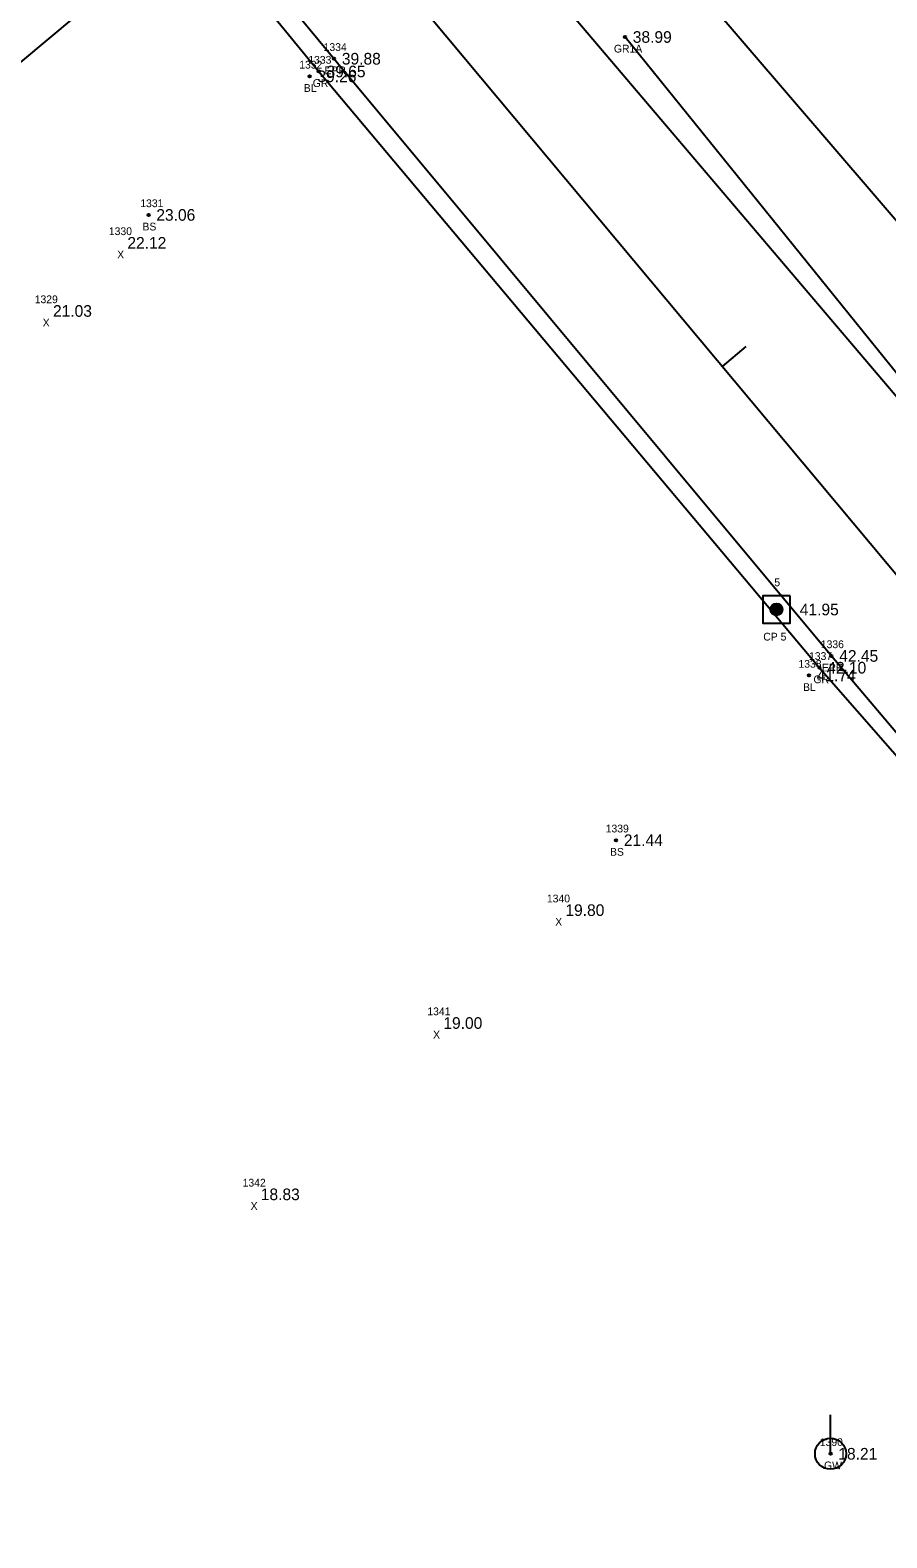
# Model space of a CAD drawing. Extents: x 2042117 to 2045853, y 303080 to 309569.
# Drawn here: x 2043251.6 to 2043361.9, y 305904.8 to 306099 of the extents above; entities that cross this region are included whole.
import ezdxf

# ---------------------------------------------------------------- set-up
doc = ezdxf.new("R2010")
doc.units = 0
for name, color, linetype in [('RD_DTM_BkLn_txCode', 7, 'Continuous'), ('RD_EX_GuardRail', 7, 'Continuous'), ('RD_EX_GuardRail_txCode', 7, 'Continuous'), ('RD_EX_Misc_txCode', 7, 'Continuous'), ('RD_EX_Road', 7, 'Continuous'), ('RD_EX_Road_txCode', 7, 'Continuous'), ('RD_EX_TX_GuardRail_ELEV', 7, 'Continuous'), ('RD_EX_TX_Misc_ELEV', 7, 'Continuous'), ('RD_EX_TX_Road_ELEV', 7, 'Continuous'), ('RD_EX_TX_UT_ELEV', 7, 'Continuous'), ('RD_EX_UT', 7, 'Continuous'), ('RD_EX_UT_txCode', 7, 'Continuous'), ('RD_EX_VEG', 7, 'Continuous'), ('RD_HC_Cl', 7, 'Continuous'), ('RD_HC_Data', 7, 'Continuous'), ('RD_HC_Data_Tic', 7, 'Continuous'), ('RD_HC_Survey', 7, 'Continuous'), ('RD_HC_Survey_ELEV', 7, 'Continuous'), ('RD_HC_Survey_txCode', 7, 'Continuous'), ('RD_SMD_Locator', 7, 'Continuous')]:
    doc.layers.add(name, color=color, linetype=linetype)

msp = doc.modelspace()

# ---------------------------------------------------------------- linework, layer by layer
at = {"layer": 'RD_EX_GuardRail'}
for points in [[(2042989.52, 306565.65), (2042994.63, 306555.31), (2043016.03, 306510.44), (2043038.99, 306465.35), (2043062.42, 306421.45), (2043086.95, 306378), (2043112.8, 306335.35), (2043139.38, 306293.6), (2043167.12, 306252.13), (2043196.01, 306211.01), (2043226.01, 306171.01), (2043257.1, 306132.34), (2043288.76, 306093.67), (2043353.25, 306016.86), (2043419.08, 305941.69), (2043443.37, 305914.98)], [(2043328.2, 306098.11), (2043376.89, 306037.83), (2043391.98, 306019.15), (2043438.03, 305959.17), (2043441.35, 305955), (2043457.81, 305935.14)]]:
    msp.add_lwpolyline(points, dxfattribs=at)
at = {"layer": 'RD_EX_Road'}
for points in [[(2043137.38, 306350.66), (2043162.88, 306309.77), (2043190.74, 306268.8), (2043219.18, 306228.69), (2043249.32, 306189.21), (2043279.47, 306150.9), (2043310.9, 306113.33), (2043375.86, 306036.86), (2043413.21, 305990.46), (2043437.78, 305959.09), (2043453.01, 305940), (2043456.21, 305936.08), (2043457.42, 305934.8)], [(2043115.12, 306336.87), (2043141.61, 306295.02), (2043169.3, 306253.51), (2043198.36, 306212.75), (2043228.29, 306172.85), (2043259.02, 306133.68), (2043290.73, 306095.31), (2043354.79, 306018.38), (2043419.43, 305942.01), (2043438.08, 305920.77), (2043442.86, 305915.34)]]:
    msp.add_lwpolyline(points, dxfattribs=at)
at = {"layer": 'RD_EX_UT'}
msp.add_line((2043354.67, 305915.6), (2043354.67, 305920.6), dxfattribs=at)
msp.add_circle((2043354.67, 305915.6), 2, dxfattribs=at)
at = {"layer": 'RD_EX_VEG'}
msp.add_lwpolyline([(2043030.11, 306588.1), (2043035.72, 306574.19), (2043060.12, 306522.02), (2043088.59, 306466.9), (2043098.93, 306441.29), (2043120.97, 306400.06), (2043177.31, 306317.21), (2043201.76, 306279.58), (2043229.83, 306237.41), (2043260.65, 306197.8), (2043289.37, 306160.32), (2043322.23, 306122.17), (2043376.5, 306058.9), (2043456.79, 305961.76), (2043477.52, 305946.76)], dxfattribs=at)
at = {"layer": 'RD_HC_Cl'}
msp.add_line((2043284.3, 306123.24), (2045221.31, 303804), dxfattribs=at)
at = {"layer": 'RD_HC_Data'}
msp.add_line((2043284.29, 306123.24), (2043173.02, 306030.31), dxfattribs=at)
at = {"layer": 'RD_HC_Data_Tic'}
msp.add_line((2043340.74, 306055.66), (2043343.81, 306058.22), dxfattribs=at)
at = {"layer": 'RD_HC_Survey'}
for p, q in [((2043346.97, 306024.18), (2043346.97, 306024.54)), ((2043346.99, 306024.1), (2043346.99, 306024.62)), ((2043347.02, 306024.04), (2043347.02, 306024.68)), ((2043347.04, 306023.99), (2043347.04, 306024.73)), ((2043347.07, 306023.95), (2043347.07, 306024.77)), ((2043347.09, 306023.91), (2043347.09, 306024.81)), ((2043347.11, 306023.88), (2043347.11, 306024.84)), ((2043347.14, 306023.85), (2043347.14, 306024.87)), ((2043347.16, 306023.82), (2043347.16, 306024.9)), ((2043347.19, 306023.8), (2043347.19, 306024.92)), ((2043347.21, 306023.78), (2043347.21, 306024.94)), ((2043347.24, 306023.76), (2043347.24, 306024.96)), ((2043347.26, 306023.74), (2043347.26, 306024.98)), ((2043347.29, 306023.72), (2043347.29, 306025)), ((2043347.31, 306023.7), (2043347.31, 306025.02)), ((2043347.34, 306023.69), (2043347.34, 306025.03)), ((2043347.36, 306023.68), (2043347.36, 306025.04)), ((2043347.39, 306023.66), (2043347.39, 306025.06)), ((2043347.41, 306023.65), (2043347.41, 306025.07)), ((2043347.44, 306023.64), (2043347.44, 306025.08)), ((2043347.46, 306023.63), (2043347.46, 306025.09)), ((2043347.49, 306023.62), (2043347.49, 306025.09)), ((2043347.51, 306023.62), (2043347.51, 306025.1)), ((2043347.54, 306023.61), (2043347.54, 306025.11)), ((2043347.56, 306023.61), (2043347.56, 306025.11)), ((2043347.58, 306023.6), (2043347.58, 306025.12)), ((2043347.61, 306023.6), (2043347.61, 306025.12)), ((2043347.63, 306023.59), (2043347.63, 306025.12)), ((2043347.66, 306023.59), (2043347.66, 306025.13)), ((2043347.68, 306023.59), (2043347.68, 306025.13)), ((2043347.71, 306023.59), (2043347.71, 306025.13)), ((2043347.73, 306023.59), (2043347.73, 306025.13)), ((2043347.76, 306023.59), (2043347.76, 306025.13)), ((2043347.78, 306023.59), (2043347.78, 306025.13)), ((2043347.81, 306023.6), (2043347.81, 306025.12)), ((2043347.83, 306023.6), (2043347.83, 306025.12)), ((2043347.86, 306023.6), (2043347.86, 306025.12)), ((2043347.88, 306023.61), (2043347.88, 306025.11)), ((2043347.91, 306023.61), (2043347.91, 306025.1)), ((2043347.93, 306023.62), (2043347.93, 306025.1)), ((2043347.96, 306023.63), (2043347.96, 306025.09)), ((2043347.98, 306023.64), (2043347.98, 306025.08)), ((2043348.01, 306023.65), (2043348.01, 306025.07)), ((2043348.03, 306023.66), (2043348.03, 306025.06)), ((2043348.05, 306023.67), (2043348.05, 306025.05)), ((2043348.08, 306023.68), (2043348.08, 306025.04)), ((2043348.1, 306023.7), (2043348.1, 306025.02)), ((2043348.13, 306023.71), (2043348.13, 306025.01)), ((2043348.15, 306023.73), (2043348.15, 306024.99)), ((2043348.18, 306023.75), (2043348.18, 306024.97)), ((2043348.2, 306023.77), (2043348.2, 306024.95)), ((2043348.23, 306023.79), (2043348.23, 306024.93)), ((2043348.25, 306023.81), (2043348.25, 306024.91)), ((2043348.28, 306023.84), (2043348.28, 306024.88)), ((2043348.3, 306023.86), (2043348.3, 306024.86)), ((2043348.33, 306023.89), (2043348.33, 306024.83)), ((2043348.35, 306023.93), (2043348.35, 306024.79)), ((2043348.38, 306023.97), (2043348.38, 306024.75)), ((2043348.4, 306024.01), (2043348.4, 306024.71)), ((2043348.43, 306024.07), (2043348.43, 306024.65)), ((2043348.45, 306024.14), (2043348.45, 306024.58)), ((2043348.48, 306024.25), (2043348.48, 306024.47))]:
    msp.add_line(p, q, dxfattribs=at)
msp.add_lwpolyline([(2043349.46, 306026.11), (2043345.96, 306026.11), (2043345.96, 306022.61), (2043349.46, 306022.61)], close=True, dxfattribs=at)
msp.add_circle((2043347.71, 306024.36), 0.769, dxfattribs=at)
at = {"layer": 'RD_SMD_Locator'}
for centre in [(2043328.2, 306098.11), (2043290.73, 306095.31), (2043287.58, 306093.04), (2043288.76, 306093.67), (2043266.83, 306075.19), (2043347.71, 306024.36), (2043354.79, 306018.38), (2043353.25, 306016.86), (2043351.89, 306015.86), (2043327.05, 305994.64), (2043354.67, 305915.6)]:
    msp.add_circle(centre, 0.15, dxfattribs=at)

# ---------------------------------------------------------------- texts
at = {"layer": 'RD_DTM_BkLn_txCode'}
for s, p in [('1332', (2043286.24, 306094.04)), ('BL', (2043286.83, 306091.04)), ('1331', (2043265.77, 306076.19)), ('BS', (2043266.05, 306073.19)), ('1338', (2043350.54, 306016.86)), ('BL', (2043351.13, 306013.86)), ('1339', (2043325.71, 305995.64)), ('BS', (2043326.27, 305992.64))]:
    msp.add_text(s, height=1, dxfattribs=at).set_placement(p)
at = {"layer": 'RD_EX_GuardRail_txCode'}
for s, p in [('GR1A', (2043326.77, 306096.11)), ('1333', (2043287.41, 306094.67)), ('GR', (2043287.98, 306091.67)), ('1337', (2043351.9, 306017.86)), ('GR', (2043352.47, 306014.86))]:
    msp.add_text(s, height=1, dxfattribs=at).set_placement(p)
at = {"layer": 'RD_EX_Misc_txCode'}
for s, p in [('1330', (2043261.72, 306072.59)), ('X', (2043262.79, 306069.59)), ('1329', (2043252.17, 306063.82)), ('X', (2043253.2, 306060.82)), ('1340', (2043318.14, 305986.63)), ('X', (2043319.21, 305983.63)), ('1341', (2043302.74, 305972.09)), ('X', (2043303.48, 305969.09)), ('1342', (2043278.95, 305950.02)), ('X', (2043279.98, 305947.02))]:
    msp.add_text(s, height=1, dxfattribs=at).set_placement(p)
at = {"layer": 'RD_EX_Road_txCode'}
for s, p in [('1334', (2043289.38, 306096.31)), ('EPR', (2043289.5, 306093.31)), ('1336', (2043353.42, 306019.38)), ('EPR', (2043353.56, 306016.38))]:
    msp.add_text(s, height=1, dxfattribs=at).set_placement(p)
at = {"layer": 'RD_EX_TX_GuardRail_ELEV'}
for s, p in [('38.99', (2043329.2, 306097.36)), ('39.65', (2043289.76, 306092.92)), ('42.10', (2043354.25, 306016.11))]:
    msp.add_text(s, height=1.5, dxfattribs=at).set_placement(p)
at = {"layer": 'RD_EX_TX_Misc_ELEV'}
for s, p in [('39.26', (2043288.58, 306092.29)), ('23.06', (2043267.83, 306074.44)), ('22.12', (2043264.1, 306070.84)), ('21.03', (2043254.52, 306062.07)), ('41.74', (2043352.89, 306015.11)), ('21.44', (2043328.05, 305993.89)), ('19.80', (2043320.52, 305984.88)), ('19.00', (2043304.8, 305970.34)), ('18.83', (2043281.29, 305948.27))]:
    msp.add_text(s, height=1.5, dxfattribs=at).set_placement(p)
at = {"layer": 'RD_EX_TX_Road_ELEV'}
for s, p in [('39.88', (2043291.73, 306094.56)), ('42.45', (2043355.79, 306017.63))]:
    msp.add_text(s, height=1.5, dxfattribs=at).set_placement(p)
at = {"layer": 'RD_EX_TX_UT_ELEV'}
msp.add_text('18.21', height=1.5, dxfattribs=at).set_placement((2043355.67, 305914.85))
at = {"layer": 'RD_EX_UT_txCode'}
for s, p in [('1390', (2043353.29, 305916.6)), ('GW', (2043353.83, 305913.6))]:
    msp.add_text(s, height=1, dxfattribs=at).set_placement(p)
at = {"layer": 'RD_HC_Survey_ELEV'}
msp.add_text('41.95', height=1.5, dxfattribs=at).set_placement((2043350.71, 306023.61))
at = {"layer": 'RD_HC_Survey_txCode'}
for s, p in [('5', (2043347.43, 306027.36)), ('CP 5', (2043346.01, 306020.36))]:
    msp.add_text(s, height=1, dxfattribs=at).set_placement(p)

doc.saveas('drawing.dxf')
